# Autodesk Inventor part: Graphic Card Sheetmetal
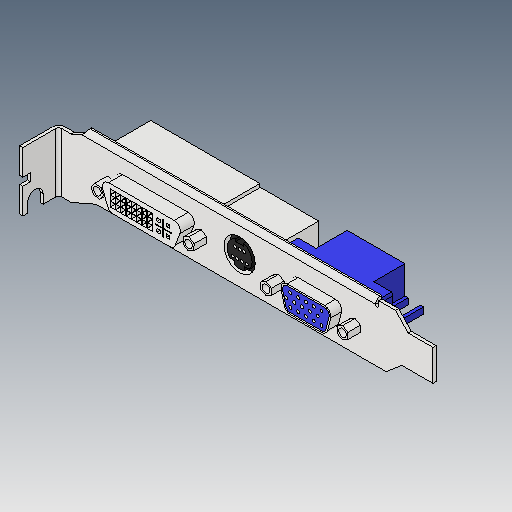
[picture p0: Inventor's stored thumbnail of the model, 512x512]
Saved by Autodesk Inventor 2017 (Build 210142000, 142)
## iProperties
Created: 2005-12
Part Number: Graphic Card Sheetmetal
Material: Generic
Document SubType Name: Modeling
Designer: DanielSeverino
Density: 1 g/cm^3
Appearance: Default
Author: DanielSeverino
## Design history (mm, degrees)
feature "Solid1"
body "Solid2"
